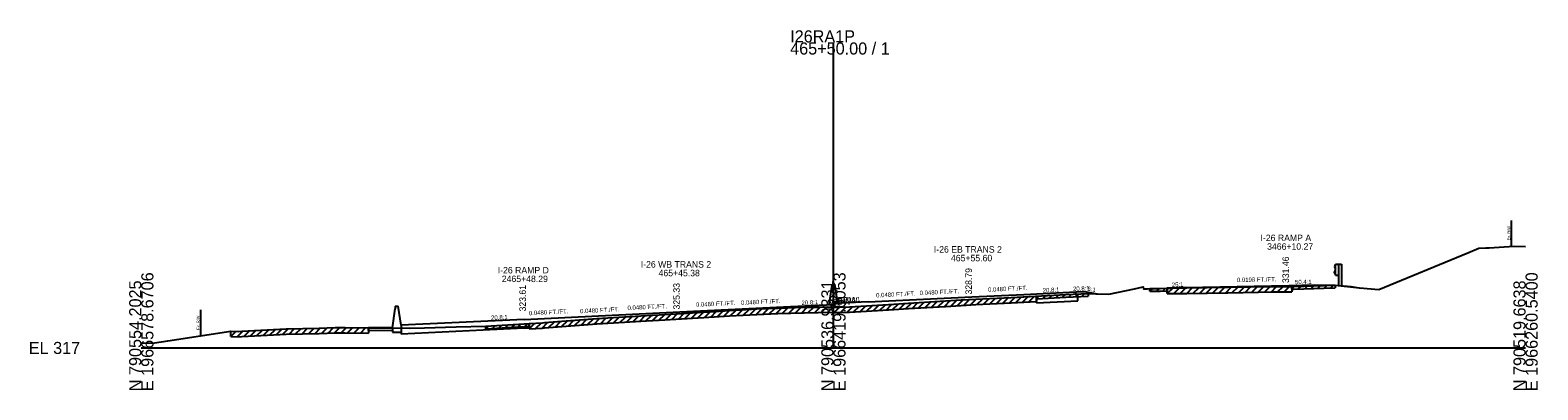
# Model space of a CAD drawing. Extents: x -44 to 4323, y -10 to 9601.
# Drawn here: x 3974.3 to 4322.8, y 3990.3 to 4073.5 of the extents above; entities that cross this region are included whole.
import ezdxf

# ---------------------------------------------------------------- set-up
doc = ezdxf.new("R2010")
doc.units = 0
for name, color, linetype in [('1', 7, 'Continuous'), ('DateStamp', 7, 'Continuous'), ('NotForConst', 7, 'Continuous'), ('QCQA', 7, 'Continuous'), ('RD_SHT_Bndy', 7, 'Continuous'), ('RD_SHT_Iplotshp', 7, 'Continuous'), ('RD_SHT_TX', 7, 'Continuous'), ('RD_XS_Base', 7, 'Continuous'), ('RD_XS_ExGround', 7, 'Continuous'), ('RD_XS_ExPaveRet', 7, 'Continuous'), ('RD_XS_MedBWall', 7, 'Continuous'), ('RD_XS_Misc_Line', 7, 'Continuous'), ('RD_XS_Pave', 7, 'Continuous'), ('RD_XS_PaveOvlay', 7, 'Continuous'), ('RD_XS_PaveShd', 7, 'Continuous'), ('RD_XS_TX_Elev_PR', 7, 'Continuous'), ('RD_XS_TX_Profile', 7, 'Continuous'), ('RD_XS_TX_ShdSlope', 7, 'Continuous'), ('RD_XS_TX_Slope', 7, 'Continuous'), ('seal', 7, 'Continuous'), ('TR SN EXTRUDED PANEL SIGNS - GROUND MOUNTED', 7, 'Continuous')]:
    doc.layers.add(name, color=color, linetype=linetype)

msp = doc.modelspace()

# ---------------------------------------------------------------- linework, layer by layer
at = {"layer": 'DateStamp'}
msp.add_lwpolyline([(4000, 4001.07), (4003.08, 4001.19), (4006.14, 4001.66), (4020.67, 4003.87), (4022.41, 4003.82), (4023.21, 4003.87), (4033.47, 4004.43), (4041.12, 4004.61), (4044.83, 4004.72), (4047.11, 4004.71), (4052.49, 4004.69), (4062.05, 4004.56), (4065.49, 4004.67), (4072.78, 4004.91), (4079.65, 4005.04), (4088.51, 4005.58), (4089.7, 4005.65), (4092.73, 4005.84), (4093.17, 4005.88), (4104.32, 4006.75), (4105.29, 4006.81), (4116.8, 4007.5), (4119.69, 4007.67), (4130.01, 4008.3), (4135.94, 4008.65), (4142.28, 4009.01), (4147.16, 4009.18), (4153.25, 4009.4), (4156.45, 4009.46), (4158.7, 4009.51), (4160, 4009.47), (4160.52, 4009.45), (4161.5, 4009.41), (4163.68, 4009.52), (4167.61, 4009.73), (4173.97, 4010.14), (4177.33, 4010.35), (4185.92, 4010.87), (4189.53, 4011.09), (4192.95, 4011.27), (4201.07, 4011.69), (4213.69, 4012.36), (4218.91, 4012.63), (4220.67, 4012.55), (4223.63, 4012.43), (4229.63, 4013.7), (4231.6, 4014.13), (4231.7, 4013.68), (4232.63, 4013.71), (4233.17, 4013.73), (4235.56, 4013.78), (4237.96, 4013.83), (4241.73, 4013.87), (4251.14, 4014.03), (4261.83, 4014.19), (4266.42, 4014.25), (4273.38, 4014.46), (4275.95, 4014.52), (4281.62, 4013.88), (4286.1, 4013.52), (4306.63, 4021.97), (4309.23, 4023.04), (4310.79, 4023.13), (4311.62, 4023.17), (4317.36, 4023.55), (4320, 4023.46)], dxfattribs=at)
at = {"layer": 'NotForConst'}
for p, q in [((4199.18, 4010.34), (4200.5, 4011.66)), ((4200.68, 4010.42), (4202, 4011.74)), ((4202.18, 4010.5), (4203.5, 4011.82)), ((4203.68, 4010.58), (4205, 4011.9)), ((4205.18, 4010.66), (4206.5, 4011.98)), ((4206.91, 4011.38), (4207.57, 4012.04)), ((4208.41, 4011.46), (4209.07, 4012.12)), ((4209.91, 4011.54), (4210.57, 4012.2)), ((4211.41, 4011.62), (4212.07, 4012.28)), ((4212.91, 4011.7), (4213.57, 4012.36)), ((4214.41, 4011.78), (4215.07, 4012.44)), ((4215.91, 4011.85), (4216.57, 4012.51)), ((4217.41, 4011.93), (4218.07, 4012.59)), ((4233.17, 4013.1), (4233.81, 4013.74)), ((4234.67, 4013.13), (4235.31, 4013.77)), ((4236.17, 4013.17), (4236.8, 4013.8)), ((4237.18, 4012.56), (4238.45, 4013.83)), ((4238.68, 4012.59), (4239.94, 4013.85)), ((4240.18, 4012.6), (4241.45, 4013.87)), ((4241.68, 4012.62), (4242.95, 4013.89)), ((4243.18, 4012.65), (4244.45, 4013.92)), ((4244.68, 4012.67), (4245.95, 4013.94)), ((4246.18, 4012.7), (4247.45, 4013.97)), ((4247.68, 4012.72), (4248.95, 4013.99)), ((4249.18, 4012.75), (4250.45, 4014.02)), ((4250.68, 4012.77), (4251.95, 4014.04)), ((4252.18, 4012.79), (4253.45, 4014.06)), ((4253.68, 4012.82), (4254.95, 4014.09)), ((4255.18, 4012.84), (4256.45, 4014.11)), ((4256.68, 4012.86), (4257.95, 4014.13)), ((4258.18, 4012.89), (4259.45, 4014.16)), ((4259.68, 4012.91), (4260.95, 4014.18)), ((4261.18, 4012.93), (4262.45, 4014.2)), ((4262.68, 4012.95), (4263.95, 4014.22)), ((4264.19, 4012.97), (4265.45, 4014.24)), ((4265.94, 4013.62), (4266.58, 4014.26)), ((4267.44, 4013.66), (4268.09, 4014.3)), ((4268.94, 4013.7), (4269.59, 4014.35)), ((4270.45, 4013.75), (4271.09, 4014.39)), ((4271.95, 4013.79), (4272.59, 4014.44)), ((4273.45, 4013.84), (4274.09, 4014.48)), ((4274.95, 4013.87), (4275.59, 4014.51)), ((4127.16, 4006.87), (4128.49, 4008.2)), ((4128.66, 4006.96), (4129.99, 4008.29)), ((4130.16, 4007.05), (4131.49, 4008.38)), ((4131.66, 4007.14), (4132.99, 4008.47)), ((4133.16, 4007.23), (4134.49, 4008.56)), ((4134.66, 4007.32), (4135.99, 4008.65)), ((4136.16, 4007.41), (4137.49, 4008.73)), ((4137.66, 4007.49), (4138.99, 4008.82)), ((4139.16, 4007.58), (4140.49, 4008.9)), ((4140.66, 4007.66), (4141.99, 4008.99)), ((4142.16, 4007.75), (4143.46, 4009.05)), ((4143.66, 4007.81), (4144.96, 4009.1)), ((4145.16, 4007.86), (4146.46, 4009.15)), ((4146.67, 4007.91), (4147.96, 4009.21)), ((4148.17, 4007.96), (4149.46, 4009.26)), ((4149.67, 4008.02), (4150.96, 4009.31)), ((4151.17, 4008.07), (4152.46, 4009.37)), ((4152.67, 4008.13), (4153.95, 4009.41)), ((4154.17, 4008.16), (4155.44, 4009.44)), ((4155.67, 4008.19), (4156.94, 4009.47)), ((4157.17, 4008.23), (4158.45, 4009.5)), ((4158.67, 4008.26), (4159.88, 4009.47)), ((4160.17, 4008.21), (4161.38, 4009.42)), ((4161.67, 4008.17), (4162.98, 4009.49)), ((4163.17, 4008.25), (4164.49, 4009.56)), ((4164.67, 4008.32), (4165.99, 4009.65)), ((4166.17, 4008.41), (4167.49, 4009.73)), ((4167.67, 4008.49), (4169.01, 4009.82)), ((4169.17, 4008.58), (4170.51, 4009.92)), ((4170.67, 4008.68), (4172.01, 4010.01)), ((4172.17, 4008.77), (4173.51, 4010.11)), ((4173.67, 4008.87), (4175.01, 4010.2)), ((4175.17, 4008.97), (4176.51, 4010.3)), ((4176.67, 4009.06), (4178.01, 4010.39)), ((4178.17, 4009.15), (4179.5, 4010.48)), ((4179.67, 4009.25), (4181, 4010.58)), ((4181.17, 4009.34), (4182.5, 4010.67)), ((4182.67, 4009.43), (4184, 4010.76)), ((4184.17, 4009.52), (4185.5, 4010.85)), ((4185.67, 4009.61), (4187.01, 4010.94)), ((4187.17, 4009.7), (4188.51, 4011.03)), ((4188.67, 4009.79), (4190, 4011.12)), ((4190.18, 4009.88), (4191.49, 4011.19)), ((4191.68, 4009.95), (4192.99, 4011.27)), ((4193.18, 4010.03), (4194.5, 4011.35)), ((4194.68, 4010.11), (4196, 4011.43)), ((4196.18, 4010.19), (4197.5, 4011.51)), ((4197.68, 4010.27), (4199, 4011.59)), ((4041.67, 4003.37), (4042.96, 4004.66)), ((4043.17, 4003.42), (4044.46, 4004.7)), ((4044.67, 4003.46), (4045.92, 4004.71)), ((4046.17, 4003.46), (4047.42, 4004.71)), ((4047.67, 4003.46), (4048.92, 4004.71)), ((4049.17, 4003.45), (4050.42, 4004.7)), ((4050.67, 4003.45), (4051.92, 4004.7)), ((4079.65, 4004.42), (4080.31, 4005.08)), ((4081.15, 4004.51), (4081.82, 4005.17)), ((4082.65, 4004.6), (4083.32, 4005.26)), ((4084.15, 4004.69), (4084.82, 4005.36)), ((4085.65, 4004.78), (4086.32, 4005.45)), ((4087.15, 4004.87), (4087.82, 4005.54)), ((4088.65, 4004.96), (4089.32, 4005.63)), ((4089.65, 4004.4), (4090.99, 4005.73)), ((4091.15, 4004.49), (4092.49, 4005.83)), ((4092.65, 4004.59), (4094.01, 4005.94)), ((4094.15, 4004.71), (4095.51, 4006.06)), ((4095.65, 4004.82), (4097.01, 4006.18)), ((4097.15, 4004.94), (4098.51, 4006.3)), ((4098.65, 4005.06), (4100.01, 4006.42)), ((4100.15, 4005.18), (4101.51, 4006.53)), ((4101.65, 4005.29), (4103.01, 4006.65)), ((4103.15, 4005.41), (4104.51, 4006.76)), ((4104.66, 4005.52), (4105.98, 4006.85)), ((4106.16, 4005.61), (4107.49, 4006.94)), ((4107.66, 4005.7), (4108.99, 4007.03)), ((4109.16, 4005.79), (4110.49, 4007.12)), ((4110.66, 4005.88), (4111.99, 4007.21)), ((4112.16, 4005.97), (4113.49, 4007.3)), ((4113.66, 4006.06), (4114.99, 4007.39)), ((4115.16, 4006.15), (4116.49, 4007.48)), ((4116.66, 4006.24), (4117.99, 4007.57)), ((4118.16, 4006.33), (4119.49, 4007.66)), ((4119.66, 4006.42), (4120.99, 4007.75)), ((4121.16, 4006.51), (4122.49, 4007.84)), ((4122.66, 4006.6), (4123.99, 4007.93)), ((4124.16, 4006.69), (4125.49, 4008.02)), ((4125.66, 4006.78), (4126.99, 4008.11)), ((4020.67, 4002.62), (4021.88, 4003.83)), ((4022.17, 4002.57), (4023.48, 4003.88)), ((4023.67, 4002.64), (4024.99, 4003.96)), ((4025.17, 4002.72), (4026.49, 4004.05)), ((4026.67, 4002.81), (4027.99, 4004.13)), ((4028.17, 4002.89), (4029.49, 4004.21)), ((4029.67, 4002.97), (4030.99, 4004.3)), ((4031.17, 4003.05), (4032.49, 4004.38)), ((4032.67, 4003.14), (4033.98, 4004.44)), ((4034.17, 4003.2), (4035.45, 4004.48)), ((4035.67, 4003.23), (4036.95, 4004.51)), ((4037.17, 4003.27), (4038.45, 4004.55)), ((4038.67, 4003.3), (4039.95, 4004.58)), ((4040.17, 4003.33), (4041.45, 4004.62))]:
    msp.add_line(p, q, dxfattribs=at)
at = {"layer": 'QCQA'}
for p, q in [((4192.95, 4011.27), (4201.07, 4011.69)), ((4201.07, 4011.69), (4206.91, 4012)), ((4119.69, 4007.67), (4130.01, 4008.3)), ((4130.01, 4008.3), (4135.94, 4008.65)), ((4135.94, 4008.65), (4142.28, 4009.01)), ((4142.28, 4009.01), (4147.16, 4009.18)), ((4147.16, 4009.18), (4153.25, 4009.4)), ((4153.25, 4009.4), (4156.45, 4009.46)), ((4156.45, 4009.46), (4158.7, 4009.51)), ((4158.7, 4009.51), (4160, 4009.47)), ((4160, 4009.47), (4160.52, 4009.45)), ((4160.52, 4009.45), (4161.5, 4009.41)), ((4161.5, 4009.41), (4163.68, 4009.52)), ((4163.68, 4009.52), (4167.61, 4009.73)), ((4167.61, 4009.73), (4173.97, 4010.14)), ((4173.97, 4010.14), (4177.33, 4010.35)), ((4177.33, 4010.35), (4185.92, 4010.87)), ((4185.92, 4010.87), (4189.53, 4011.09)), ((4189.53, 4011.09), (4192.95, 4011.27)), ((4089.65, 4005.65), (4089.7, 4005.65)), ((4089.65, 4005.65), (4089.65, 4004.62)), ((4089.7, 4005.65), (4092.73, 4005.84)), ((4092.73, 4005.84), (4093.17, 4005.88)), ((4093.17, 4005.88), (4104.32, 4006.75)), ((4104.32, 4006.75), (4105.29, 4006.81)), ((4105.29, 4006.81), (4116.8, 4007.5)), ((4116.8, 4007.5), (4119.69, 4007.67))]:
    msp.add_line(p, q, dxfattribs=at)
at = {"layer": 'RD_SHT_Bndy'}
for p, q in [((4160, 4000), (4160, 4070.66)), ((4000, 4000), (4160, 4000)), ((4160, 4000), (4320, 4000))]:
    msp.add_line(p, q, dxfattribs=at)
at = {"layer": 'RD_SHT_Iplotshp'}
for p, q in [((4206.91, 4012), (4206.91, 4010.75)), ((4206.91, 4011.38), (4206.91, 4012)), ((4206.91, 4011.38), (4213.69, 4011.74)), ((4213.69, 4011.74), (4218.91, 4012.01)), ((4218.91, 4012.63), (4218.91, 4012.01)), ((4233.17, 4013.1), (4233.17, 4013.73)), ((4233.17, 4013.1), (4235.56, 4013.16)), ((4235.56, 4013.16), (4237.18, 4013.19)), ((4237.18, 4012.56), (4237.18, 4013.81)), ((4237.18, 4013.81), (4237.18, 4013.19)), ((4237.18, 4012.56), (4237.96, 4012.58)), ((4237.96, 4012.58), (4241.73, 4012.62)), ((4241.73, 4012.62), (4251.14, 4012.78)), ((4251.14, 4012.78), (4261.83, 4012.94)), ((4261.83, 4012.94), (4265.94, 4013)), ((4265.94, 4014.25), (4265.94, 4013)), ((4265.94, 4013.62), (4265.94, 4014.25)), ((4265.94, 4013.62), (4266.42, 4013.63)), ((4266.42, 4013.63), (4273.38, 4013.84)), ((4273.38, 4013.84), (4275.95, 4013.9)), ((4275.95, 4014.52), (4275.95, 4013.9)), ((4147.16, 4007.93), (4153.25, 4008.15)), ((4153.25, 4008.15), (4156.45, 4008.21)), ((4156.45, 4008.21), (4158.7, 4008.26)), ((4158.7, 4008.26), (4160, 4008.22)), ((4160, 4008.22), (4160.52, 4008.2)), ((4160.52, 4008.2), (4161.5, 4008.16)), ((4161.5, 4008.16), (4163.68, 4008.27)), ((4163.68, 4008.27), (4167.61, 4008.48)), ((4167.61, 4008.48), (4173.97, 4008.89)), ((4173.97, 4008.89), (4177.33, 4009.1)), ((4177.33, 4009.1), (4185.92, 4009.62)), ((4185.92, 4009.62), (4189.53, 4009.84)), ((4189.53, 4009.84), (4192.95, 4010.02)), ((4192.95, 4010.02), (4201.07, 4010.44)), ((4201.07, 4010.44), (4206.91, 4010.75)), ((4052.49, 4004.69), (4052.49, 4003.44)), ((4079.65, 4004.42), (4079.65, 4005.04)), ((4079.65, 4004.42), (4088.51, 4004.95)), ((4088.51, 4004.95), (4089.65, 4005.03)), ((4089.65, 4004.4), (4089.65, 4005.65)), ((4089.65, 4005.65), (4089.65, 4005.03)), ((4093.17, 4004.63), (4104.32, 4005.5)), ((4104.32, 4005.5), (4105.29, 4005.56)), ((4105.29, 4005.56), (4116.8, 4006.25)), ((4116.8, 4006.25), (4119.69, 4006.42)), ((4119.69, 4006.42), (4130.01, 4007.05)), ((4130.01, 4007.05), (4135.94, 4007.4)), ((4135.94, 4007.4), (4142.28, 4007.76)), ((4142.28, 4007.76), (4147.16, 4007.93)), ((4020.67, 4002.62), (4020.67, 4003.87)), ((4020.67, 4002.62), (4022.41, 4002.57)), ((4022.41, 4002.57), (4023.21, 4002.62)), ((4023.21, 4002.62), (4033.47, 4003.18)), ((4033.47, 4003.18), (4041.12, 4003.36)), ((4041.12, 4003.36), (4044.83, 4003.47)), ((4044.83, 4003.47), (4047.11, 4003.46)), ((4047.11, 4003.46), (4052.49, 4003.44)), ((4089.65, 4004.4), (4089.7, 4004.4)), ((4089.7, 4004.4), (4092.73, 4004.59)), ((4092.73, 4004.59), (4093.17, 4004.63))]:
    msp.add_line(p, q, dxfattribs=at)
at = {"layer": 'RD_XS_Base'}
for p, q in [((4276.09, 4019.24), (4275.82, 4018.8)), ((4275.82, 4018.8), (4275.82, 4018.69)), ((4275.82, 4018.69), (4276.09, 4018.25)), ((4276.09, 4019.4), (4276.76, 4019.4)), ((4276.09, 4016.83), (4276.09, 4019.4)), ((4276.76, 4019.4), (4277.42, 4019.4)), ((4276.76, 4019.4), (4276.76, 4014.46)), ((4277.42, 4019.4), (4277.42, 4014.35)), ((4275.82, 4017.54), (4276.09, 4017.98)), ((4275.82, 4017.43), (4275.82, 4017.54)), ((4276.09, 4016.99), (4275.82, 4017.43)), ((4276.09, 4016.83), (4276.76, 4016.83))]:
    msp.add_line(p, q, dxfattribs=at)
at = {"layer": 'RD_XS_ExPaveRet'}
msp.add_line((4058.05, 4004.62), (4058.05, 4003.62), dxfattribs=at)
at = {"layer": 'RD_XS_Misc_Line'}
for p, q in [((4206.91, 4010.46), (4206.91, 4012)), ((4216, 4012.38), (4216, 4012.94)), ((4216, 4012.38), (4216.5, 4012.4)), ((4216.5, 4010.92), (4216.5, 4012.4)), ((4237.3, 4013.81), (4237.3, 4013.83)), ((4271.3, 4014.4), (4271.3, 4014.58)), ((4206.91, 4010.46), (4216.5, 4010.92)), ((4052.49, 4004.03), (4052.49, 4004.69)), ((4058.05, 4003.95), (4052.49, 4004.03)), ((4088.47, 4004.57), (4060.05, 4003.2)), ((4088.47, 4004.57), (4089.65, 4004.62))]:
    msp.add_line(p, q, dxfattribs=at)
at = {"layer": 'RD_XS_Pave'}
for p, q in [((4218, 4013.04), (4220.96, 4012.54)), ((4275.95, 4014.52), (4279.7, 4014.22)), ((4279.7, 4014.22), (4281.99, 4013.84))]:
    msp.add_line(p, q, dxfattribs=at)
at = {"layer": 'RD_XS_PaveOvlay'}
for p, q in [((4316.71, 4029.51), (4316.71, 4023.51)), ((4013.7, 4008.81), (4013.7, 4002.81))]:
    msp.add_line(p, q, dxfattribs=at)
at = {"layer": 'RD_XS_PaveShd'}
for p, q in [((4216, 4012.94), (4218, 4013.04)), ((4237.3, 4013.83), (4237.09, 4013.81)), ((4271.3, 4014.58), (4275.95, 4014.52))]:
    msp.add_line(p, q, dxfattribs=at)
at = {"layer": 'RD_XS_TX_Elev_PR'}
for p, q in [((4204, 4012.36), (4216, 4012.94)), ((4241.3, 4013.99), (4237.3, 4013.83)), ((4265.3, 4014.46), (4271.3, 4014.58)), ((4148.47, 4009.48), (4160, 4010.04)), ((4168, 4010.64), (4160, 4010.25)), ((4160, 4010.25), (4160, 4010.04)), ((4058.05, 4004.62), (4052.49, 4004.69)), ((4088.47, 4006.61), (4060.05, 4005.24)), ((4060.05, 4005.24), (4060.05, 4003.2)), ((4058.05, 4004.62), (4058.05, 4003.95))]:
    msp.add_line(p, q, dxfattribs=at)
at = {"layer": 'RD_XS_TX_ShdSlope'}
for p, q in [((4159, 4009.99), (4159.67, 4014.54)), ((4159.67, 4014.75), (4160.33, 4014.75)), ((4159.67, 4014.54), (4159.67, 4014.75)), ((4161, 4010.3), (4160.33, 4014.75)), ((4058.05, 4004.62), (4058.72, 4009.07)), ((4058.72, 4009.69), (4059.39, 4009.69)), ((4058.72, 4009.69), (4058.72, 4009.07)), ((4060.05, 4005.24), (4059.39, 4009.69)), ((4060.05, 4005.24), (4060.05, 4003.62)), ((4058.05, 4003.62), (4060.05, 4003.62))]:
    msp.add_line(p, q, dxfattribs=at)
at = {"layer": 'RD_XS_TX_Slope'}
for p, q in [((4168, 4010.64), (4192, 4011.79)), ((4192, 4011.79), (4204, 4012.36)), ((4241.3, 4013.99), (4265.3, 4014.46)), ((4088.47, 4006.61), (4124.47, 4008.33)), ((4124.47, 4008.33), (4148.47, 4009.48))]:
    msp.add_line(p, q, dxfattribs=at)

# ---------------------------------------------------------------- texts
at = {"layer": '1'}
for s, p in [('I-26 RAMP A', (4258.73, 4024.71)), ('I-26 EB TRANS 2', (4183.22, 4022.04)), ('3466+10.27', (4260.26, 4022.71)), ('I-26 RAMP D', (4082.4, 4017.23)), ('I-26 WB TRANS 2', (4115.46, 4018.58)), ('465+55.60', (4187.17, 4020.04)), ('2465+48.29', (4083.34, 4015.23)), ('465+45.38', (4119.58, 4016.58))]:
    msp.add_text(s, height=1.5, dxfattribs=at).set_placement(p)
at = {"layer": 'RD_SHT_Bndy'}
for s, p in [('I26RA1P', (4150, 4070.66)), ('465+50.00 / 1', (4150, 4067.86)), ('EL 317', (3974, 3998.6))]:
    msp.add_text(s, height=2.8, dxfattribs=at).set_placement(p)
for s, p in [('N 790554.2025', (4000, 3990)), ('E 1966578.6706', (4002.8, 3990)), ('N 790536.9331', (4160, 3990)), ('E 1966419.6053', (4162.8, 3990)), ('N 790519.6638', (4320, 3990)), ('E 1966260.5400', (4322.8, 3990))]:
    msp.add_text(s, height=2.8, rotation=90, dxfattribs=at).set_placement(p)
at = {"layer": 'RD_SHT_TX'}
msp.add_text('326.47', height=1, rotation=90, dxfattribs=at).set_placement((4161, 4009.47))
at = {"layer": 'RD_XS_ExGround'}
for rotation, p in [(2.7481, (4162.41, 4010.62)), (2.7481, (4208.41, 4012.83)), (2.7475, (4152.65, 4009.94)), (2.7475, (4080.88, 4006.49))]:
    msp.add_text('20.8:1', height=1, rotation=rotation, dxfattribs=at).set_placement(p)
at = {"layer": 'RD_XS_MedBWall'}
msp.add_text('20.8:1', height=1, rotation=2.7481, dxfattribs=at).set_placement((4215.41, 4013.16))
at = {"layer": 'RD_XS_PaveOvlay'}
for p in [(4316.46, 4024.89), (4013.45, 4004.19)]:
    msp.add_text('Ex. R/W ', height=0.65, rotation=90, dxfattribs=at).set_placement(p)
at = {"layer": 'RD_XS_TX_Profile'}
for s, p in [('EBW', (4161, 4010.3)), ('WBW', (4159, 4009.99))]:
    msp.add_text(s, height=1.5, dxfattribs=at).set_placement(p)
at = {"layer": 'seal'}
for s, p in [(' 331.46', (4265.3, 4014.46)), (' 328.79', (4192, 4011.79)), ('323.61', (4088.9, 4008.43)), (' 325.33', (4124.47, 4008.33))]:
    msp.add_text(s, height=1.5, rotation=90, dxfattribs=at).set_placement(p)
at = {"layer": 'TR SN EXTRUDED PANEL SIGNS - GROUND MOUNTED'}
for s, rotation, p in [('25:1', 2.2903, (4238.24, 4014.11)), ('0.0198 FT./FT.', 1.1364, (4253.28, 4015.23)), ('50.4:1', 1.1364, (4266.72, 4014.74)), ('0.0480 FT./FT.', 2.7481, (4169.89, 4011.67)), ('0.0480 FT./FT.', 2.7481, (4179.95, 4012.21)), ('0.0480 FT./FT.', 2.7481, (4195.77, 4012.97)), ('6:1', 350.5377, (4218.67, 4013.24)), ('0.0480 FT./FT.', 2.75, (4089.62, 4007.55)), ('0.0480 FT./FT.', 2.75, (4101.46, 4008.01)), ('0.0480 FT./FT.', 2.7475, (4112.42, 4008.76)), ('0.0480 FT./FT.', 2.7475, (4128.24, 4009.51)), ('0.0480 FT./FT.', 2.75, (4138.66, 4009.95))]:
    msp.add_text(s, height=1, rotation=rotation, dxfattribs=at).set_placement(p)

doc.saveas('drawing.dxf')
